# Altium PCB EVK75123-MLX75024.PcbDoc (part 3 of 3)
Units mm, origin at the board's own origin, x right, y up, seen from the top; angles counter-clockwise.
Board outline 80 x 50 mm, 8 copper layers (Top Layer, GND_T, Signal Layer 1, Vcc1, Vcc2, Signal Layer 2, GND_B, Bottom Layer), stack 1.548 mm thick; 222 components, 135 nets, 746 pads, 778 vias.
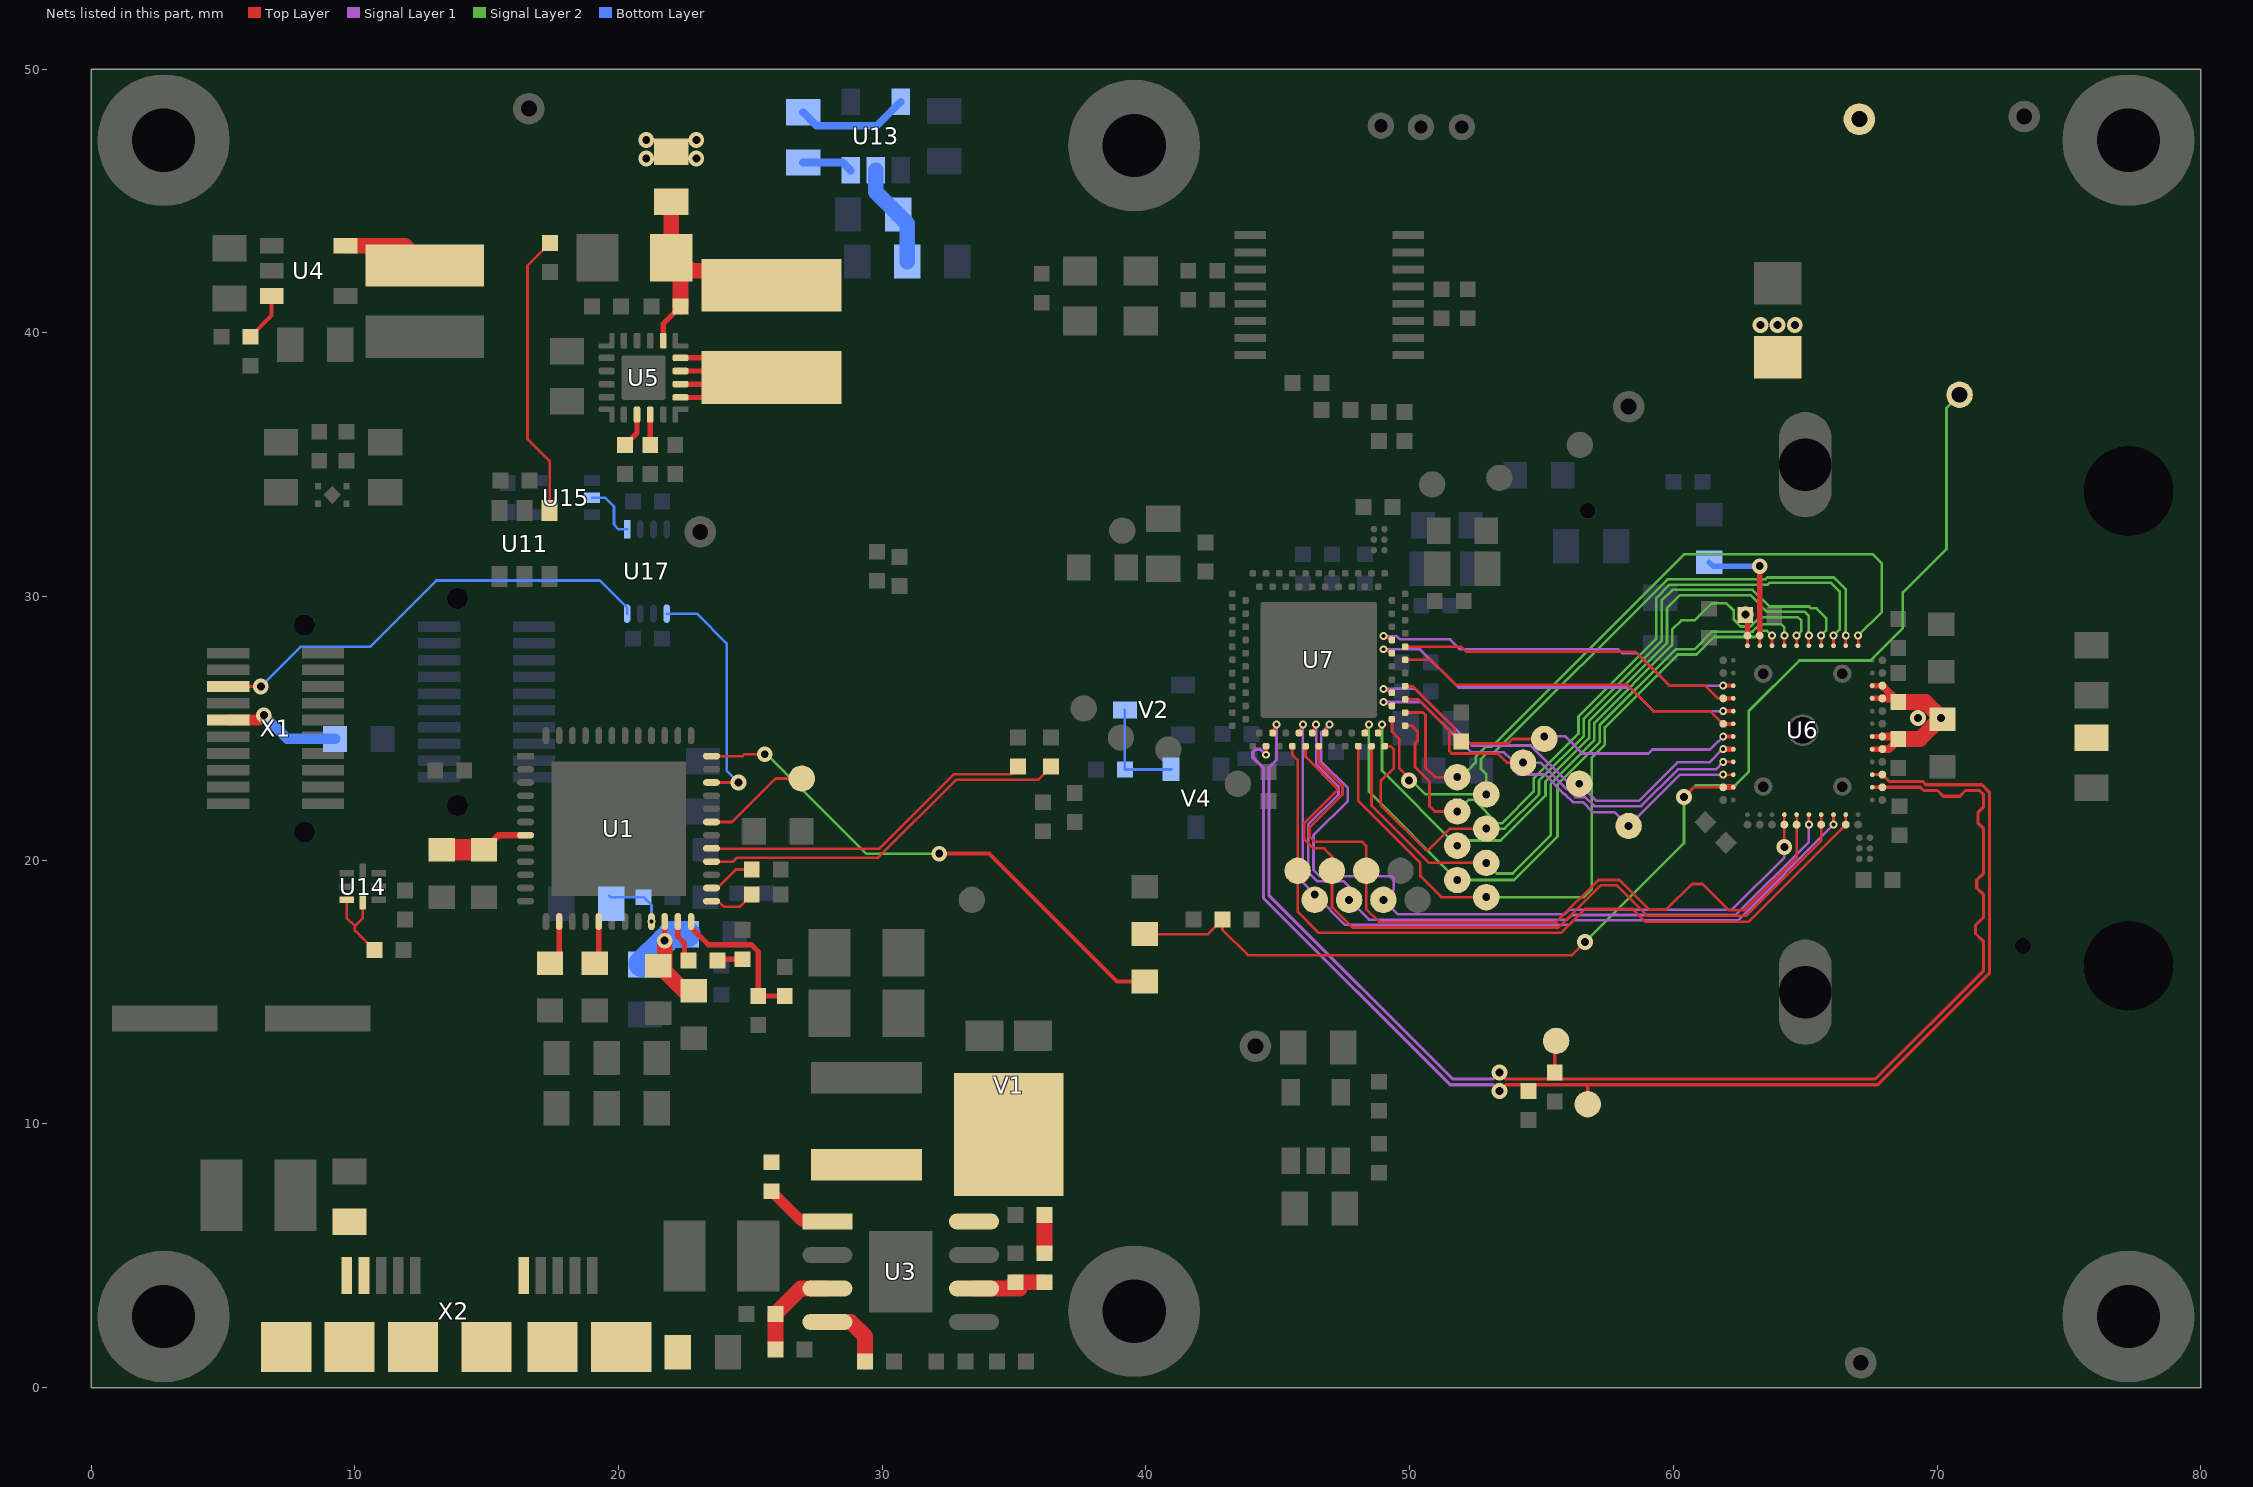
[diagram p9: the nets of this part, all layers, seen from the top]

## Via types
v1: diameter 0.6, hole 0.3, Top Layer to Bottom Layer, tented both sides, 705 vias
v2: diameter 0.3, hole 0.15, Top Layer to Bottom Layer, tented both sides, 49 vias
v3: diameter 0.6, hole 0.3, Top Layer to Bottom Layer, 9 vias
v4: diameter 0.7, hole 0.33, Top Layer to Bottom Layer, 9 vias
v5: diameter 0.5, hole 0.2, Top Layer to Bottom Layer, tented both sides, 6 vias

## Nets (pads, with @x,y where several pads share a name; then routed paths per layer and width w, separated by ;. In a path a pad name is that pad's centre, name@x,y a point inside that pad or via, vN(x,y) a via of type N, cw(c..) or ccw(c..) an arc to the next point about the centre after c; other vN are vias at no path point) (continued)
MLX.COL2: COL2.1 pad.0@64.203,21.35 U6.26 U7.B36 | length 29.1
  Top Layer w0.1: U7.B36@46.8,24.825 v2(46.95,25.15) ; v1(64.203,20.503) pad.0@64.203,21.35 U6.26@64.203,21.733
  Signal Layer 1 w0.1: v2(46.95,25.15) 46.65,24.85 46.65,23.733 47.65,22.733 47.65,22.25 46.35,20.95 46.35,19.633 46.583,19.4 49.3,19.4 49.4,19.3 49.4,18.9 v1(49,18.5) 49.55,17.95 55.875,17.95 56.05,18.125 62.225,18.125 64.203,20.103 v1(64.203,20.503)
MLX.COL3: COL3.1 pad.0@64.669,21.35 U6.27 U7.A39 | length 30
  Top Layer w0.1: U7.A39@46.55,24.325 46.55,23.712 47.45,22.812 47.45,22.5 46.2,21.25 46.2,20.9 46.4,20.7 48.2,20.7 48.35,20.55 COL3.1@48.35,19.6 48.35,18.15 48.85,17.65 55.554,17.65 57.154,19.25 57.95,19.25 59.075,18.125 59.725,18.125 60.7,19.1 61.1,19.1 62.1,18.1 62.683,18.1 64.669,20.086 pad.0@64.669,21.35 U6.27@64.669,21.733
MLX.COL4: COL4.1 pad.0@65.135,21.35 U6.28 U7.B35 | length 29.1
  Top Layer w0.1: U7.B35@46.3,24.825 v2(46.45,25.15) ; v2(65.135,21.35) U6.28@65.135,21.733
  Signal Layer 1 w0.1: v2(46.45,25.15) 46.45,23.65 47.3,22.8 47.3,22.5 46.15,21.35 46.15,19.55 46.5,19.2 47.5,19.2 47.7,19 v1(47.7,18.5) 48.45,17.75 55.958,17.75 56.133,17.925 62.36,17.925 65.135,20.701 v2(65.135,21.35)
MLX.COL5: COL5.1 pad.0@65.601,21.35 U6.29 U7.A38 | length 30
  Top Layer w0.1: U7.A38@46.05,24.325 46.05,23.929 47.25,22.729 47.25,22.65 46,21.4 46,20.8 46.35,20.45 46.75,20.45 47.05,20.15 COL5.1@47.05,19.6 47.05,18.231 47.831,17.45 55.636,17.45 57.236,19.05 57.85,19.05 59,17.9 62.766,17.9 65.601,20.736 pad.0@65.601,21.35 U6.29@65.601,21.733
MLX.COL6: COL6.1 pad.0@66.067,21.35 U6.30 U7.B34 | length 29.1
  Top Layer w0.1: U7.B34@45.8,24.825 v2(45.95,25.15) ; v2(66.067,21.35) U6.30@66.067,21.733
  Signal Layer 1 w0.1: v2(45.95,25.15) 45.95,19.15 v1(46.4,18.7) 47.55,17.55 56.041,17.55 56.216,17.725 62.442,17.725 v2(66.067,21.35)
MLX.COL7: COL7.1 pad.0@66.534,21.35 U6.31 U7.A37 | length 29.9
  Top Layer w0.1: U7.A37@45.55,24.325 45.55,24 45.75,23.8 COL7.1@45.75,19.6 45.75,18.05 46.55,17.25 55.741,17.25 56.641,18.15 58.449,18.15 58.924,17.675 62.859,17.675 pad.0@66.534,21.35 U6.31@66.534,21.733
MLX.CS: CS.1 pad.0@61.886,22.766 R6.2 R8.1 R17.2 R55.1 U6.21 | length 49
  Top Layer w0.1: R8.1@39.95,17.2 42.35,17.2 R6.2@42.9,17.75 42.9,17.363 43.864,16.4 44.236,16.4 56.15,16.4 v1(56.65,16.9) ; v1(60.4,22.4) 60.766,22.766 pad.0@61.886,22.766
  Top Layer w0.2: pad.0@61.886,22.766 U6.21@62.268,22.766
  Signal Layer 2 w0.1: v1(56.65,16.9) 60.4,20.65 v1(60.4,22.4) 60.85,22.85 62.35,22.85 62.85,23.35 62.85,25.65 64.774,27.574 67.474,27.574 68.7,28.8 68.7,30.15 70.35,31.8 70.35,37.15 CS.1@70.85,37.65
MLX.DMIX_N: DM-.1 pad.0@67.919,22.766 R54.1 U6.34 U7.B32 | length 51.9
  Top Layer w0.12: U7.B32@44.8,24.825 v2(44.95,25.15) ; v1(53.4,11.95) 53.64,11.71 67.66,11.71 71.76,15.81 71.76,16.911 71.45,17.221 71.45,17.54 71.76,17.85 71.76,18.69 71.5,18.95 71.5,19.25 71.76,19.51 71.76,21.19 71.55,21.4 71.55,21.814 71.76,22.023 71.76,22.491 71.605,22.645 71.074,22.645 70.854,22.425 70.231,22.425 70.011,22.645 69.48,22.645 69.359,22.766 pad.0@67.919,22.766 U6.34@67.536,22.766 ; R54.1@55.5,11.95 55.5,13.1 DM-.1@55.55,13.15
  Signal Layer 1 w0.12: 44.69,23.54 44.67,23.52 44.67,18.661 51.621,11.71 53.16,11.71 v1(53.4,11.95) ; 44.69,23.541 44.95,23.801 v2(44.95,25.15)
MLX.DMIX_P: DM+.1 pad.0@67.919,23.248 R48.1 U6.35 U7.A35 | length 51.4
  Top Layer w0.12: v2(44.55,24) U7.A35@44.55,24.325 ; v1(53.4,11.25) 53.64,11.49 67.751,11.49 71.98,15.719 71.98,22.582 71.696,22.865 69.571,22.865 69.45,22.986 68.18,22.986 pad.0@67.919,23.248 U6.35@67.536,23.248 ; DM+.1@56.75,10.75 56.75,11.49
  Signal Layer 1 w0.12: v2(44.55,24) 44.339,24.211 44.15,24.211 44.05,24.111 44.05,23.912 44.45,23.512 44.45,18.57 51.53,11.49 53.16,11.49 v1(53.4,11.25)
MLX.L_EN: LEN.1 pad.0@61.886,24.693 R56.1 U6.17 U7.A4 | length 14.1
  Top Layer w0.1: U7.A4@49.825,26.6 50.108,26.6 51.7,25.008 51.7,24.75 R56.1@51.95,24.5 52.025,24.425 53.725,24.425 53.9,24.6 LEN.1@55.1,24.6
  Top Layer w0.15: v2(61.886,24.693) U6.17@62.268,24.693
  Signal Layer 1 w0.1: v1(55.1,24.7) 55.9,24.7 56.55,24.05 59.05,24.05 59.2,24.2 61.386,24.2 61.693,24.507 61.7,24.507 v2(61.886,24.693)
MLX.PFLUSH: FLUSH.1 pad.0@61.886,24.211 U6.18 U7.B3 | length 16.2
  Top Layer w0.1: v2(49,26.5) U7.B3@49.325,26.35
  Top Layer w0.2: v2(61.886,24.211) U6.18@62.268,24.211
  Signal Layer 1 w0.1: v2(49,26.5) 50.208,26.5 52.358,24.35 54.586,24.35 56.034,22.902 v1(56.429,22.902) 57.081,22.25 58.684,22.25 60.145,23.711 61.361,23.711 61.861,24.211 v2(61.886,24.211)
MLX.ROW0: pad.0@63.737,28.517 ROW0.1 U6.8 U7.A42 | length 27.5
  Top Layer w0.1: U7.A42@48.05,24.325 48.05,22.25 50.4,19.9 50.4,19.4 51.2,18.6 v1(52.9,18.6) ; U6.8@63.737,28.135 v2(63.737,28.517)
  Signal Layer 2 w0.1: v1(52.9,18.6) 56.6,18.6 56.901,18.901 56.901,23.888 57.4,24.386 57.4,25.036 60.164,27.8 60.872,27.8 61.537,28.465 63.088,28.465 63.323,28.7 63.554,28.7 v2(63.737,28.517)
MLX.ROW1: pad.0@64.203,28.517 ROW1.1 U6.7 U7.B39 | length 26.3
  Top Layer w0.1: U7.B39@48.3,24.825 v2(48.45,25.15) ; U6.7@64.203,28.135 v2(64.203,28.517)
  Signal Layer 2 w0.1: v2(48.45,25.15) 48.45,22.6 v1(51.8,19.25) 53.95,19.25 55.6,20.9 55.6,22.869 57.2,24.469 57.2,25.119 60.081,28 60.789,28 61.454,28.665 63.005,28.665 63.29,28.95 64.081,28.95 64.203,28.828 v2(64.203,28.517)
MLX.ROW2: pad.0@64.669,28.517 ROW2.1 U6.6 U7.A43 | length 27.5
  Top Layer w0.1: U7.A43@48.55,24.325 48.55,22.078 50.728,19.9 v1(52.9,19.9) ; U6.6@64.669,28.135 v2(64.669,28.517)
  Signal Layer 2 w0.1: v1(52.9,19.9) 53.3,19.5 53.9,19.5 55.35,20.95 55.35,22.902 57,24.552 57,25.202 59.953,28.155 59.953,28.753 60.3,29.1 60.802,29.1 61.452,29.75 62,29.75 62.285,29.465 62.285,29.128 62.549,28.865 62.922,28.865 63.278,29.221 64.711,29.221 64.85,29.082 64.85,28.698 v2(64.669,28.517)
MLX.ROW3: pad.0@65.135,28.517 ROW3.1 U6.5 U7.B40 | length 26.3
  Top Layer w0.1: U7.B40@48.8,24.825 v2(48.95,25.15) ; U6.5@65.135,28.135 v2(65.135,28.517)
  Signal Layer 2 w0.1: v2(48.95,25.15) 48.95,23.4 v1(51.8,20.55) 52,20.75 53.45,20.75 55.15,22.45 55.15,22.985 56.8,24.635 56.8,25.285 59.753,28.238 59.753,29.561 60.242,30.05 62.922,30.05 63.552,29.421 64.979,29.421 65.135,29.265 v2(65.135,28.517)
MLX.ROW4: pad.0@65.601,28.517 ROW4.1 U6.4 U7.A44 | length 27.5
  Top Layer w0.1: U7.A44@49.05,24.325 49.275,24.325 49.4,24.2 49.4,23.5 48.9,23 48.9,22.1 50.6,20.4 50.731,20.4 51.531,21.2 v1(52.9,21.2) ; U6.4@65.601,28.135 v2(65.601,28.517)
  Signal Layer 2 w0.1: v1(52.9,21.2) 53.6,21.2 54.9,22.5 54.9,23.018 56.6,24.718 56.6,25.368 59.553,28.321 59.553,29.842 59.961,30.25 63.005,30.25 63.634,29.621 65.143,29.621 65.214,29.55 65.43,29.55 65.787,29.193 65.787,28.703 v2(65.601,28.517)
MLX.ROW5: pad.0@66.067,28.517 ROW5.1 U6.3 U7.A1 | length 27.5
  Top Layer w0.1: U7.A1@49.825,25.1 50.085,25.1 50.3,24.885 50.3,24.55 50.2,24.45 50.2,23.536 50.75,22.986 50.75,22.05 50.95,21.85 v1(51.8,21.85) ; U6.3@66.067,28.135 v2(66.067,28.517)
  Signal Layer 2 w0.1: v1(51.8,21.85) 52.25,22.3 52.436,22.3 53.336,21.4 53.5,21.4 54.7,22.6 54.7,23.101 56.4,24.801 56.4,25.451 59.353,28.404 59.353,29.953 59.85,30.45 63.564,30.45 63.634,30.521 65.979,30.521 66.3,30.2 66.3,28.75 v2(66.067,28.517)
MLX.ROW6: pad.0@66.534,28.517 ROW6.1 U6.2 U7.B1 | length 26.3
  Top Layer w0.1: U7.B1@49.325,25.35 49.325,24.875 49.6,24.6 49.6,23.5 50.07,23.03 v1(49.975,23.03) ; U6.2@66.534,28.135 v2(66.534,28.517)
  Signal Layer 2 w0.1: v1(49.975,23.03) 50.07,23.03 50.6,22.5 v1(52.9,22.5) 52.9,23.264 52.7,23.464 52.7,23.836 52.964,24.1 53.217,24.1 59.767,30.65 63.481,30.65 63.552,30.721 66.079,30.721 66.534,30.266 v2(66.534,28.517)
MLX.ROW7: pad.0@67,28.517 ROW7.1 U6.1 U7.A2 | length 27.5
  Top Layer w0.1: U7.A2@49.825,25.6 50.5,25.6 50.6,25.5 50.6,23.5 50.95,23.15 v1(51.8,23.15) ; U6.1@67,28.135 v2(67,28.517)
  Signal Layer 2 w0.1: v1(51.8,23.15) 52.088,23.438 52.238,23.438 52.5,23.7 52.5,23.919 52.881,24.3 53.1,24.3 60.4,31.6 67.559,31.6 67.9,31.259 67.9,29.418 v2(67,28.517)
MLX.RST: pad.0@61.886,23.729 RST.1 U6.19 U7.A3 | length 15.3
  Top Layer w0.1: U7.A3@49.825,26.1 50.325,26.1 51.5,24.925 51.5,24.138 51.588,24.05 53.336,24.05 53.686,23.7 v1(54.3,23.7) ; v2(61.886,23.729) 62.205,23.729 62.237,23.698 U6.19@62.268,23.729
  Signal Layer 1 w0.1: v1(54.3,23.7) 54.954,23.7 55.951,22.702 55.975,22.702 56.277,22.4 56.648,22.4 56.998,22.05 58.767,22.05 60.165,23.448 61.604,23.448 v2(61.886,23.729)
MLX.SHUT: pad.0@61.886,23.248 SHUT.1 U6.20 U7.B2 | length 16.6
  Top Layer w0.1: v2(49,26) U7.B2@49.325,25.85 ; v2(61.886,23.248) U6.20@62.268,23.248
  Signal Layer 1 w0.1: v2(49,26) 50.425,26 52.325,24.1 53.564,24.1 53.85,23.814 53.85,23.514 54.114,23.25 55.121,23.25 55.869,22.502 55.891,22.502 56.193,22.2 56.565,22.2 56.945,21.82 57.78,21.82 v1(58.3,21.3) 60.248,23.248 v2(61.886,23.248)
MODE: R1.1 R5.2 U1.24 | length 5.8
  Top Layer w0.2: U1.24@22.75,17.675 22.75,17.45 23.4,16.8 25.033,16.8 25.3,16.533 R1.1@25.3,14.85 R5.2@26.3,14.85
NERR: U1.34 U17.5 | length 9.2
  Top Layer w0.1: U1.34@23.525,22.95 v1(24.55,22.95)
  Bottom Layer w0.1: U17.5@21.825,29.35 22.967,29.35 24.1,28.217 24.1,23.4 v1(24.55,22.95)
nERRH: U17.8 X1.15 | length 17.4
  Top Layer w0.1: X1.15@5.2,26.588 v1(6.438,26.588)
  Bottom Layer w0.1: v1(6.438,26.588) 7.942,28.092 10.583,28.092 13.095,30.605 19.295,30.605 20.325,29.575 U17.8@20.325,29.35
NetC4_1: C4.1 R50.2 | length 1.1
  Top Layer w0.2: C4.1@23.6,16.25 R50.2@24.7,16.25
NetC4_2: C4.2 U1.23 | length 1.5
  Top Layer w0.2: U1.23@22.25,17.675 22.25,17.1 22.5,16.85 C4.2@22.5,16.25
NetC5_2: C5.2 U1.17 | length 1.6
  Top Layer w0.2: C5.2@19.1,16.1 19.25,16.25 U1.17@19.25,17.675
NetC7_2: C7.2 U1.14 | length 1.7
  Top Layer w0.2: C7.2@17.4,16.1 17.75,16.45 U1.14@17.75,17.675
NetC14_1: C14.1 U13.3 | length 1.9
  Bottom Layer w0.3: C14.1@27,46.458 28.5,46.458 U13.3@28.8,46.158
NetC14_2: C14.2 U13.5 | length 4.3
  Bottom Layer w0.3: C14.2@27,48.358 27.508,47.85 29.792,47.85 U13.5@30.7,48.758
NetC16_2: C16.2 C18.2 U1.7 | length 3.4
  Top Layer w0.25: C16.2@14.9,20.4 15.45,20.95 U1.7@16.475,20.95
  Top Layer w0.8: C18.2@13.3,20.4 C16.2@14.9,20.4
NetC38_2: C38.2 pad.0@62.805,28.517 U6.10 | length 1.2
  Top Layer w0.1: U6.10@62.805,28.135 pad.0@62.805,28.517
  Top Layer w0.2: C38.2@62.721,29.3 62.805,29.216 pad.0@62.805,28.517
  Top Layer w0.6: C38.2@62.721,29.3 v1(62.735,29.315)
NetC40_2: C40.2 U5.10 | length 1.3
  Top Layer w0.2: C40.2@20.25,35.75 20.7,36.2 U5.10@20.7,36.9
NetC61_1: C61.1 U3.1 | length 2.6
  Top Layer w0.4: C61.1@25.8,7.45 26.945,6.305 U3.1@27.92,6.305
NetC70_2: C70.2 R29.2 | length 1.1
  Top Layer w0.6: R29.2@36.15,5.15 C70.2@36.15,6.25
NetC71_2: C71.2 R29.1 U3.6 | length 2.9
  Top Layer w0.6: U3.6@33.48,3.765 C71.2@35.215,3.765 ; C71.2@35,4 R29.1@36.15,4
NetC77_2: C77.2 R37.1 R38.1 U13.2 | length 4
  Bottom Layer w0.6: U13.2@29.75,46.158 29.75,45.335 C77.2@30.6,44.485 30.95,44.135 R37.1@30.95,42.7
NetL2_1: L2.1 U4.5 | length 3.3
  Top Layer w0.6: U4.5@9.65,43.3 11.9,43.3 L2.1@12.65,42.55
NetL14_2: L14.2 X2.1 X2.2 X2.6
NetL15_1: L15.1 X2.11 X2.12 X2.13 X2.14 X2.15 X2.16
NetL17_2: L17.2 X1.11 | length 4.5
  Top Layer w0.4: X1.11@5.2,25.318 6.368,25.318 v1(6.55,25.5)
  Bottom Layer w0.4: v1(6.55,25.5) 6.55,25.486 7.436,24.6 L17.2@9.25,24.6
NetR3_1: pad.0@63.271,28.517 R3.1 U6.9 | length 5
  Top Layer w0.1: U6.9@63.271,28.135 pad.0@63.271,28.517
  Top Layer w0.2: pad.0@63.271,28.517 v1(63.271,31.15)
  Bottom Layer w0.2: R3.1@61.35,31.3 61.5,31.15 v1(63.271,31.15)
NetR14_1: R14.1 V2.3 V4.1 | length 4
  Bottom Layer w0.1: V2.3@39.2,25.7 R14.1@39.2,23.439 40.939,23.439 V4.1@40.95,23.45
NetR16_2: R16.2 R20.2 U4.3 | length 1.9
  Top Layer w0.15: R20.2@6.05,39.85 6.85,40.65 U4.3@6.85,41.4
NetR18_2: R18.2 U3.4 | length 2.6
  Top Layer w0.6: U3.4@27.92,2.495 28.805,2.495 29.35,1.95 R18.2@29.35,1
NetR19_2: R19.2 U14.7 U14.8 | length 3.4
  Top Layer w0.1: U14.7@9.7,18.5 9.7,17.8 10,17.5 ; U14.8@10.3,18.4 10.3,17.8 10,17.5 ; R19.2@10.744,16.594 10,17.338 10,17.5
NetR32_1: R32.1 R36.1 U3.3 | length 3.5
  Top Layer w0.6: R36.1@25.95,1.7 R32.1@25.95,2.8 26.915,3.765 U3.3@27.92,3.765
NetR41_2: R41.2 U1.25 | length 1.8
  Top Layer w0.1: U1.25@23.525,18.45 23.781,18.45 24,18.231 24.581,18.231 R41.2@25.05,18.7
NetR42_2: R42.2 U1.26 | length 1.8
  Top Layer w0.1: U1.26@23.525,18.95 23.75,18.95 24.45,19.65 R42.2@25.05,19.65
NetU15_2: U15.2 U17.1 | length 2.2
  Bottom Layer w0.1: U15.2@19,33.75 19.492,33.75 19.827,33.415 19.827,32.731 20.008,32.55 U17.1@20.325,32.55
NINT: nINT.1 U1.31 | length 4.1
  Top Layer w0.1: U1.31@23.525,21.45 24.302,21.45 25.952,23.1 nINT.1@26.95,23.1
NPD: C21.2 R2.1 U1.21 | length 2.3
  Bottom Layer w0.1: C21.2@19.65,18.65 19.7,18.6 R2.1@20.85,18.6 ; R2.1@20.95,18.6 21.25,18.3 v2(21.25,17.675)
OUT0: pad.0@61.886,25.656 U6.15 U7.B6 | length 14.6
  Top Layer w0.1: v2(49,28) U7.B6@49.325,27.85
  Top Layer w0.15: v2(61.886,25.656) U6.15@62.268,25.656
  Signal Layer 1 w0.1: v2(49,28) 50.398,28 51.848,26.55 58.35,26.55 59.244,25.656 v2(61.886,25.656)
OUT1: pad.0@61.886,25.174 U6.16 U7.A6 | length 13.4
  Top Layer w0.1: U7.A6@49.825,27.6 50.798,27.6 51.748,26.65 58.25,26.65 59.244,25.656 61.391,25.656 61.872,25.174 pad.0@61.886,25.174
  Top Layer w0.15: pad.0@61.886,25.174 U6.16@62.268,25.174
OUT2: pad.0@61.886,26.138 U6.14 U7.A7 | length 13.3
  Top Layer w0.1: U7.A7@49.825,28.1 51.95,28.1 52.147,27.903 58.565,27.903 59.848,26.62 61.198,26.62 61.68,26.138 pad.0@61.886,26.138
  Top Layer w0.15: pad.0@61.886,26.138 U6.14@62.268,26.138
OUT3: pad.0@61.886,26.62 U6.13 U7.B7 | length 14.4
  Top Layer w0.1: v2(49,28.5) U7.B7@49.325,28.35
  Top Layer w0.15: v2(61.886,26.62) U6.13@62.268,26.62
  Signal Layer 1 w0.1: v2(49,28.5) 49.5,28.5 49.625,28.375 51.525,28.375 51.9,28 57.904,28 58.054,27.85 58.618,27.85 59.848,26.62 v2(61.886,26.62)
PGMIX: R27.1 U5.11 | length 1.2
  Top Layer w0.2: R27.1@21.2,35.75 U5.11@21.2,36.9
SER.D3: R44.2 U1.28 | length 14.4
  Top Layer w0.1: U1.28@23.525,19.95 24.35,19.95 24.5,20.1 29.847,20.1 32.797,23.05 35.9,23.05 R44.2@36.4,23.55
SER.D4: R45.2 U1.29 | length 12.9
  Top Layer w0.1: U1.29@23.535,20.44 29.89,20.44 32.71,23.26 34.86,23.26 R45.2@35.15,23.55
  Top Layer w0.12: U1.29@23.525,20.45 U1.29@23.535,20.44
SERIO3: R8.2 U1.36 | length 20
  Top Layer w0.1: U1.36@23.525,23.95 24.7,23.95 24.77,24.02 v1(25.545,24.02)
  Top Layer w0.15: v1(32.161,20.25) 34.05,20.25 38.9,15.4 R8.2@39.95,15.4
  Signal Layer 2 w0.1: v1(25.545,24.02) 25.616,24.02 29.386,20.25 v1(32.161,20.25)
SW5V: C61.2 L3.1 U3.8 V1.2
SWMIX: L4.1 U5.13 U5.14 U5.15 U5.16 | length 13.9
  Top Layer w0.2: U5.13@22.35,37.55 25.05,37.55 L4.1@25.55,38.05 ; U5.14@22.35,38.05 L4.1@25.55,38.05 ; U5.15@22.35,38.55 L4.1@25.55,38.55 ; U5.16@22.35,39.05 25.05,39.05 L4.1@25.55,38.55 ; L4.1@25.55,38.05 L4.1@25.8,38.3 L4.1@25.55,38.55
V_MIX: R9.2 U11.1 | length 10.8
  Top Layer w0.1: U11.1@17.387,33.258 17.387,35.143 16.55,35.98 16.55,42.55 R9.2@17.4,43.4
VDD33: C3.1 C84.2 C85.2 L9.2 U1.22 | length 5.4
  Top Layer w0.2: v1@21.75,17 U1.22@21.75,17.675
  Top Layer w0.6: v1(21.75,16.95) 21.75,15.79 22.49,15.05 C3.1@22.85,15.05
  Bottom Layer w1: C85.2@20.875,16.075 v1(21.75,16.95) 22,17.2 L9.2@22.6,17.2
VMIX: C23.2 C34.2 C36.2 C37.2 C89.1 pad.0@67.919,24.211 pad.0@67.919,24.693 pad.0@67.919,26.62 pad.0@67.919,26.138 R49.1 U6.37 U6.38 U6.41 U6.42 VMIXH.1 | length 8.1
  Top Layer w0.2: U6.37@67.536,24.211 pad.0@67.919,24.211 ; U6.38@67.536,24.693 pad.0@67.919,24.693 ; U6.41@67.536,26.138 pad.0@67.919,26.138 ; U6.42@67.536,26.62 pad.0@67.919,26.62
  Top Layer w0.3: pad.0@67.919,24.211 68.17,24.211 C34.2@68.559,24.6 ; pad.0@67.919,24.693 C34.2@68.499,24.693 ; pad.0@67.919,26.138 C36.2@68.4,26.138 ; pad.0@67.919,26.62 C36.2@68.538,26
  Top Layer w0.6: C36.2@68.538,26 69.55,26 v1(70.15,25.4) 69.35,24.6 C34.2@68.559,24.6
  other v1: 69.275,25.4 63.3,40.3 63.95,40.3 64.6,40.3 21.05,46.613 22.95,46.613 21.05,47.313 22.95,47.313
VOMIX: C35.2 L4.2 R25.2 R49.2 U5.1 | length 8.7
  Top Layer w0.2: U5.1@21.7,39.7 21.7,40.35 R25.2@22.35,41
  Top Layer w0.6: R49.2@22,44.963 C35.2@22,42.85 ; R25.2@22.35,41 22.35,42.5 C35.2@22,42.85 ; L4.2@24.85,42.35 22.75,42.35 22.25,42.85 C35.2@22,42.85
pads on no net: LH1.4 LH1.8 LH2.PS1 LH2.PS2 U1.3 U1.4 U1.5 U1.11 U1.12 U1.13 U1.16 U1.27 U1.43 U1.44 U2.1 U5.A1 U5.A2 U5.A3 U5.A4 U7.A23 U8.C1 U9.C1 U10.8 U10.9 U10.12 U10.14 U10.15 U10.16 U12.4 U15.1 X1.A1 X1.A2 X2.4 X4.9 X4.10 X4.11 X4.12 X4.13 X4.14 X4.15 X4.16 X4.17 X4.19 X4.A1 X4.A2
copper on no net:
  other v1: 41.6,29.7 51.6,39.85 52.3,39.85

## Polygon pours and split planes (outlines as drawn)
no net on BotDimHUM "spare_HUM" (hatched 45Degree grid 0.4 track 0.05, remove dead copper, pour order 0): 80,45 74.7,45 74.7,30.5 58.5,30.5 58.5,18.5 74.7,18.5 74.7,5 80,5
GND on Bottom Layer "GND" (solid, remove dead copper, pour order 21): 0.2,49.8 79.8,49.8 79.8,37.8 79.8,0.2 71,0.2 0.2,0.2 0.2,11.2
24V on Bottom Layer "24V" (solid, remove dead copper, pour order 16): 26.65,2.25 10.05,2.25 5.8,6.5 5.8,20.8 7.7,22.7 10.25,25.25 14,25.25 14,22.175 10.95,19.125 10.95,11.1 14.45,7.6 21.35,7.6 25.45,7.6 26.2,6.85 26.65,6.4 26.65,3.9
GND on Top Layer "GND" (solid, remove dead copper, pour order 17): 0.2,49.8 79.8,49.8 79.8,37.8 79.8,0.2 71,0.2 0.2,0.2 0.2,11.2
GND on Signal Layer 2 "GND" (solid, remove dead copper, pour order 19): 0.2,49.8 79.8,49.8 79.8,37.8 79.8,0.2 71,0.2 0.2,0.2 0.2,11.2
GND on Signal Layer 1 "GND" (solid, remove dead copper, pour order 18): 0.2,49.8 79.8,49.8 79.8,37.8 79.8,0.2 71,0.2 0.2,0.2 0.2,11.2
GND on GND_T (split plane): 79.49,0.51 0.51,0.51 0.51,49.49 79.49,49.49
1V8 on Vcc1 (split plane): 2.193,39.093 2.224,39.069 2.261,39.054 2.3,39.049 7.481,39.049 10.436,36.093 10.468,36.069 10.504,36.054 10.543,36.049 22.187,36.049 23.193,35.043 23.224,35.019 23.261,35.004 23.3,34.999 40.35,34.999 40.389,35.004 40.426,35.019 40.457,35.043 44.613,39.199 53.187,39.199 54.799,37.587 54.799,34.5 54.804,34.461 54.819,34.424 54.843,34.393 55.061,34.175 53.887,33.001 52.163,33.001 51.551,33.613 51.551,34.75 51.546,34.789 51.531,34.826 51.507,34.857 51.258,35.106 51.227,35.13 51.19,35.145 51.151,35.15 50.549,35.15 50.51,35.145 50.473,35.13 50.442,35.106 48.843,33.507 46.543,31.207 46.519,31.176 46.513,31.161 46.504,31.139 46.499,31.1 46.499,29.665 46.504,29.625 46.513,29.604 46.519,29.589 46.543,29.558 47.658,28.443 47.689,28.419 47.725,28.404 47.765,28.399 49.999,28.399 49.999,26.518 50.004,26.479 50.019,26.443 50.043,26.411 55.611,20.843 55.643,20.819 55.679,20.804 55.718,20.799 69.124,20.799 69.124,0.301 0.301,0.301 0.301,40.985
VMIX on Vcc1 (split plane): 79.699,0.301 69.426,0.301 69.426,23.925 69.421,23.964 69.412,23.986 69.406,24.001 69.382,24.032 63.601,29.813 63.601,30.45 63.596,30.489 63.581,30.526 63.557,30.557 59.832,34.282 59.801,34.306 59.786,34.312 59.764,34.321 59.725,34.326 55.338,34.326 55.101,34.563 55.101,37.65 55.096,37.689 55.085,37.715 55.081,37.726 55.057,37.757 53.357,39.457 53.326,39.481 53.311,39.487 53.289,39.496 53.25,39.501 44.55,39.501 44.511,39.496 44.489,39.487 44.474,39.481 44.443,39.457 40.287,35.301 23.363,35.301 22.357,36.307 22.326,36.331 22.289,36.346 22.25,36.351 10.606,36.351 7.65,39.307 7.619,39.331 7.582,39.346 7.543,39.351 2.363,39.351 0.301,41.413 0.301,49.699 79.699,49.699
GND on Vcc1 (split plane): 63.299,30.387 63.299,29.75 63.304,29.711 63.313,29.689 63.319,29.674 63.343,29.643 69.124,23.862 69.124,21.101 55.781,21.101 50.301,26.581 50.301,28.499 51.5,28.499 51.539,28.504 51.561,28.513 51.576,28.519 51.607,28.543 54.013,30.949 55.55,30.949 55.589,30.954 55.611,30.963 55.626,30.969 55.657,30.993 56.857,32.193 56.881,32.224 56.896,32.261 56.901,32.3 56.901,34.024 59.662,34.024
1V8A on Vcc1 (split plane): 51.249,34.687 51.249,33.55 51.254,33.511 51.269,33.474 51.293,33.443 51.993,32.743 52.024,32.719 52.061,32.704 52.1,32.699 53.95,32.699 53.989,32.704 54.011,32.713 54.026,32.719 54.057,32.743 55.338,34.024 56.599,34.024 56.599,32.363 55.487,31.251 53.95,31.251 53.911,31.246 53.885,31.235 53.874,31.231 53.843,31.207 51.437,28.801 50.15,28.801 50.111,28.796 50.074,28.781 50.043,28.757 49.987,28.701 47.827,28.701 46.801,29.727 46.801,31.037 49.057,33.293 50.611,34.847 51.089,34.847
5V0 on Vcc2 (split plane): 6.599,43.537 6.599,41.813 3.643,38.857 3.619,38.826 3.604,38.789 3.599,38.75 3.599,34.75 3.604,34.711 3.619,34.674 3.643,34.643 4.593,33.693 4.624,33.669 4.639,33.663 4.661,33.654 4.7,33.649 7.175,33.649 7.214,33.654 7.251,33.669 7.282,33.693 13.838,40.249 23,40.249 23.039,40.254 23.076,40.269 23.107,40.293 26.513,43.699 30.037,43.699 30.53,43.206 30.53,41.669 23.066,34.205 22.409,34.205 22.051,34.563 22.051,35.3 22.046,35.339 22.031,35.376 22.007,35.407 21.557,35.857 21.526,35.881 21.489,35.896 21.45,35.901 14.45,35.901 14.411,35.896 14.374,35.881 14.343,35.857 12.893,34.407 12.869,34.376 12.854,34.339 12.849,34.3 12.849,32.35 12.849,30.613 8.093,25.857 8.069,25.826 8.054,25.789 8.049,25.75 8.049,13.6 8.054,13.561 8.069,13.524 8.093,13.493 14.093,7.493 14.124,7.469 14.161,7.454 14.2,7.449 24.75,7.449 24.789,7.454 24.811,7.463 24.826,7.469 24.857,7.493 27.257,9.893 27.281,9.924 27.296,9.961 27.301,10 27.301,17.387 27.863,17.949 29.287,17.949 39.143,8.093 39.174,8.069 39.211,8.054 39.25,8.049 45.337,8.049 46.174,7.212 46.174,0.301 0.301,0.301 0.301,44.299 5.837,44.299
1V8D on Vcc2 (split plane): 49.749,30.945 48.311,29.507 46.668,27.864 46.644,27.833 46.638,27.818 46.629,27.796 46.624,27.757 46.624,27.438 43.55,24.364 41.351,26.563 41.351,31.237 41.613,31.499 42.507,31.499 44.555,29.451 44.586,29.427 44.601,29.42 44.623,29.411 44.662,29.406 46.358,29.406 46.397,29.411 46.418,29.42 46.433,29.427 46.465,29.451 48.975,31.961 49.749,31.961
3V3 on Vcc2 (split plane): 79.699,0.301 46.477,0.301 46.477,7.274 46.472,7.314 46.457,7.35 46.433,7.381 45.507,8.307 45.476,8.331 45.439,8.346 45.4,8.351 39.313,8.351 29.457,18.207 29.426,18.231 29.411,18.237 29.389,18.246 29.35,18.251 27.8,18.251 27.761,18.246 27.724,18.231 27.693,18.207 27.043,17.557 27.019,17.526 27.004,17.489 26.999,17.45 26.999,10.063 24.687,7.751 14.263,7.751 8.351,13.663 8.351,25.687 13.107,30.443 13.131,30.474 13.146,30.511 13.151,30.55 13.151,32.35 13.151,34.237 14.513,35.599 21.387,35.599 21.749,35.237 21.749,34.5 21.754,34.461 21.763,34.439 21.769,34.424 21.793,34.393 22.239,33.947 22.27,33.923 22.307,33.908 22.346,33.903 23.128,33.903 23.167,33.908 23.189,33.917 23.204,33.923 23.235,33.947 30.788,41.5 30.812,41.531 30.827,41.568 30.832,41.607 30.832,43.269 30.827,43.308 30.812,43.345 30.788,43.376 30.207,43.957 30.176,43.981 30.161,43.987 30.139,43.996 30.1,44.001 26.45,44.001 26.411,43.996 26.374,43.981 26.343,43.957 22.937,40.551 13.775,40.551 13.736,40.546 13.699,40.531 13.668,40.507 7.112,33.951 4.763,33.951 3.901,34.813 3.901,38.687 6.857,41.643 6.881,41.674 6.896,41.711 6.901,41.75 6.901,43.6 6.896,43.639 6.881,43.676 6.857,43.707 6.007,44.557 5.976,44.581 5.961,44.587 5.939,44.596 5.9,44.601 0.301,44.601 0.301,49.699 79.699,49.699
3V3A on Vcc2 (split plane): 61.649,28.937 61.649,27.413 46.187,11.951 43.563,11.951 43.301,12.213 43.301,13.936 45.307,15.942 45.331,15.973 45.346,16.01 45.351,16.049 45.351,18.387 48.507,21.543 48.531,21.574 48.546,21.611 48.551,21.65 48.551,25.75 48.547,25.783 51.457,28.693 51.481,28.724 51.496,28.761 51.501,28.8 51.501,30.337 51.813,30.649 57.2,30.649 57.239,30.654 57.276,30.669 57.307,30.693 58.6,31.986
3V3CC on Vcc2 (split plane): 48.249,25.687 48.249,21.713 45.137,18.601 43.463,18.601 42.151,19.913 42.151,21.437 43.657,22.943 43.681,22.975 43.696,23.011 43.702,23.05 43.702,24.087 46.775,27.161
1V8ADC on Vcc2 (split plane): 58.449,32.887 58.449,32.263 57.137,30.951 51.75,30.951 51.711,30.946 51.685,30.935 51.674,30.931 51.643,30.907 51.243,30.507 51.219,30.476 51.213,30.461 51.204,30.439 51.199,30.4 51.199,28.863 48.35,26.014 46.926,27.438 46.926,27.695 48.525,29.293 50.007,30.775 50.031,30.807 50.046,30.843 50.051,30.882 50.051,34.086 50.714,34.749 56.587,34.749
GND on GND_B (split plane): 79.49,0.51 0.51,0.51 0.51,49.49 79.49,49.49

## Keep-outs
Keep-Out Layer:
  the board outline again, w0.2

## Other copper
Top Layer:
  rectangle net GND: 63.05,22.425 66.746,27.425
  region net GND: 36.45,13.95 33.15,13.95 33.15,12.75 36.45,12.75
  region net 24V: 10.45,8.7 6.95,8.7 6.95,7.7 10.45,7.7
  region net MH2: 42.55,47.1 cw(c39.55,47.1) 39.55,44.1 cw(c39.55,47.1) 36.55,47.1 36.55,49.8 42.55,49.8
  region net MH6: 36.55,2.9 cw(c39.55,2.9) 39.55,5.9 cw(c39.55,2.9) 42.55,2.9 42.55,0.2 36.55,0.2
  region net MH3: 74.25,2.7 cw(c77.25,2.7) 77.25,5.7 79.796,5.7 79.796,0.204 74.25,0.204
  region net MH5: 74.25,47.3 ccw(c77.25,47.3) 77.25,44.3 79.796,44.3 79.796,49.796 74.25,49.796
  region net MH1: 5.75,2.7 ccw(c2.75,2.7) 2.75,5.7 0.204,5.7 0.204,0.204 5.75,0.204
  region net MH4: 5.75,47.3 cw(c2.75,47.3) 2.75,44.3 0.204,44.3 0.204,49.796 5.75,49.796
  pour cut-out: 22.762,39.617 22.267,40.112 19.633,40.112 19.138,39.617 19.138,36.987 19.637,36.488 22.267,36.488 22.762,36.983
  region net 5V0: 17.4,37.4 17.4,36.45 17.7,36.15 18.4,36.15 18.7,36.45 18.7,37.4
  region net GND: 17.4,39.3 17.4,38.35 17.7,38.05 18.4,38.05 18.7,38.35 18.7,39.3
  region net GND: 19.35,42.2 20.3,42.2 20.6,42.5 20.6,43.2 20.3,43.5 19.35,43.5
  pour cut-out: 49.28,32.638 49.141,32.777 48.453,32.777 48.386,32.71 48.386,31.688 48.568,31.506 49.099,31.506 49.28,31.687
  region net VMIX: 22,47.613 21.05,47.613 20.75,47.313 20.75,46.613 21.05,46.313 22,46.313
  region net VMIX: 22,46.313 22.95,46.313 23.25,46.613 23.25,47.313 22.95,47.613 22,47.613
  region net 3V3: 69.9,27.6 74.35,27.6 75.4,26.55 75.4,25.75 74.5,25.75 73.55,26.7 69.9,26.7
  region net VMIX: 69.8,25.9 73.4,25.9 74.15,25.15 75.2,25.15 75.5,24.85 75.5,24.15 73.3,24.15 72.55,24.9 69.8,24.9
  pour cut-out: 16,25.2 24,25.2 24,17.2 16,17.2
  pour cut-out: 43.047,31.099 50.05,31.099 50.05,24.1 43.047,24.1
  region net NetL14_2: 10.55,6.85 9,6.85 9,3.55 10.55,3.55
  region net GND: 4.4,24.9 6.55,24.9 6.85,24.6 6.85,22.25 6.55,21.95 4.4,21.95
  region net 24V: 8,24.9 10.15,24.9 10.45,24.6 10.45,22.25 10.15,21.95 8,21.95
  region net 5V0: 27.2,15 27.2,11.25 27.3,11.15 30.6,11.15 30.6,12 29.55,13.05 29.55,15
  region net SW5V: 25.5,8.85 25.7,9.05 33.45,9.05 34.4,8.1 34.4,6.45 33.95,6 32.4,6 32.1,6.3 30.3,6.3 28.75,7.85 26.5,7.85
  region net VMIX: 63.05,39.75 63.05,40.35 63.2,40.5 64.7,40.5 64.85,40.35 64.85,39.75
  region net GND: 63.05,42.55 63.05,43.15 63.2,43.3 64.7,43.3 64.85,43.15 64.85,42.55
  pour cut-out: 61.95,28.35 67.75,28.35 67.75,21.5 61.95,21.5
  region net NetL14_2: 16.6,3.55 15.4,3.55 12.7,6.25 9,6.25 9,7.25 14.75,7.25 16.6,5.4
  region net 24V: 6.6,14.2 6.6,14.9 6.8,15.1 6.9,15.1 7,15.2 10.2,15.2 10.25,15.15 10.35,15.15 10.6,14.9 10.6,14.2
  region net GND: 3.45,8.15 3.45,9.1 3.15,9.4 2.45,9.4 2.15,9.1 2.15,8.15
  region net GND: 23.35,5.8 23.35,6.75 23.05,7.05 22.35,7.05 22.05,6.75 22.05,5.8
  region net GND: 22.05,4.2 22.05,3.25 22.35,2.95 23.05,2.95 23.35,3.25 23.35,4.2
  region net 24V: 24.65,6.35 24.05,6.35 23.75,6.05 23.75,3.95 24.05,3.65 24.65,3.65
  region net 24V: 7.1,8.65 6.5,8.65 6.2,8.35 6.2,6.25 6.5,5.95 7.1,5.95
  region net GND: 4.45,6.5 4.45,5.55 4.75,5.25 5.45,5.25 5.75,5.55 5.75,6.5
  region net GND: 5.75,8.1 5.75,9.05 5.45,9.35 4.75,9.35 4.45,9.05 4.45,8.1
  region net GND: 34.53,13.4 34.53,14.35 34.23,14.65 33.53,14.65 33.23,14.35 33.23,13.4
  region net GND: 36.35,13.4 36.35,14.35 36.05,14.65 35.35,14.65 35.05,14.35 35.05,13.4
  region net 5V0: 27.2,14.7 29.25,14.7 29.55,15 29.55,17.1 29.25,17.4 27.2,17.4
  region net GND: 31.45,14.75 32.05,14.75 32.35,15.05 32.35,17.15 32.05,17.45 31.45,17.45
  region net NetL15_1: 22.75,2 22.25,2.5 6.45,2.5 6.45,0.6 22.65,0.6 22.75,0.7
  pour cut-out: 67.05,21.079 67.45,21.079 67.679,20.85 67.679,20.079 67.432,19.832 67.068,19.832 66.821,20.079 66.821,20.85
  region net VMIX: 68.238,26.3 68.238,24.312 68.25,24.3 69.05,24.3 70.1,25.35 69.15,26.3
Bottom Layer:
  rectangle net GND: 63.05,22.425 66.746,27.425
  region net MH2: 36.55,47.1 ccw(c39.55,47.1) 39.55,44.1 ccw(c39.55,47.1) 42.55,47.1 42.55,49.8 36.55,49.8
  region net MH6: 42.55,2.9 ccw(c39.55,2.9) 39.55,5.9 ccw(c39.55,2.9) 36.55,2.9 36.55,0.2 42.55,0.2
  region net MH3: 77.25,5.7 ccw(c77.25,2.7) 74.25,2.7 74.25,0.2 79.796,0.2 79.796,5.7
  region net MH5: 77.25,44.3 cw(c77.25,47.3) 74.25,47.3 74.25,49.8 79.796,49.8 79.796,44.3
  region net MH1: 2.75,5.7 cw(c2.75,2.7) 5.75,2.7 5.75,0.2 0.204,0.2 0.204,5.7
  region net MH4: 2.75,44.3 ccw(c2.75,47.3) 5.75,47.3 5.75,49.8 0.204,49.8 0.204,44.3
  region net GND: 17.6,25.25 15.35,25.25 15.15,25.05 15.15,23.25 15.45,22.95 17.6,22.95
  region net 1V8A: 56.25,34.95 56.25,33.75 56.05,33.55 56.05,32.9 56.4,32.55 56.4,31.266 55.25,31.266 55.25,35 55.35,35.1 56.1,35.1
Vcc1 (plane layer: these items are gaps in the copper):
  lines w0.3: 0,41.5 2.3,39.2 7.543,39.2 10.543,36.2 22.25,36.2 23.3,35.15 40.35,35.15 44.55,39.35 53.25,39.35 54.95,37.65 54.95,34.5 55.275,34.175 ; 56.75,34.175 56.75,32.3 55.55,31.1 53.95,31.1 51.5,28.65 50.15,28.65 ; 69.275,0 69.275,23.925 63.45,29.75 63.45,30.45 59.725,34.175 55.275,34.175 ; 69.275,20.95 55.718,20.95 50.15,26.518 50.15,28.65 ; 50.15,28.65 50.05,28.55 47.765,28.55 46.65,29.665 46.65,31.1 48.95,33.4 50.549,34.999 51.151,34.999 51.4,34.75 51.4,33.55 52.1,32.85 53.95,32.85 55.275,34.175
Vcc2 (plane layer: these items are gaps in the copper):
  lines w0.3: 0,44.45 5.9,44.45 6.75,43.6 6.75,41.75 3.75,38.75 3.75,34.75 4.7,33.8 7.175,33.8 13.775,40.4 23,40.4 26.45,43.85 30.1,43.85 30.681,43.269 30.681,41.607 23.128,34.054 22.346,34.054 21.9,34.5 21.9,35.3 21.45,35.75 14.45,35.75 13,34.3 13,32.35 13,30.55 8.2,25.75 8.2,13.6 14.2,7.6 24.75,7.6 27.15,10 27.15,17.45 27.8,18.1 29.35,18.1 39.25,8.2 45.4,8.2 46.326,7.274 46.326,0 ; 48.35,25.8 51.35,28.8 51.35,30.4 51.75,30.8 57.2,30.8 58.6,32.2 ; 49.9,33.3 49.9,32.112 48.912,32.112 46.358,29.558 44.662,29.558 42.569,31.65 41.55,31.65 41.2,31.3 41.2,26.5 43.55,24.15 ; 43.55,24.15 46.775,27.375 ; 43.55,24.15 43.55,23.05 42,21.5 42,19.85 43.4,18.45 45.2,18.45 ; 45.2,18.45 45.2,16.049 43.15,13.999 43.15,12.15 43.5,11.8 46.25,11.8 61.8,27.35 61.8,29 58.6,32.2 ; 45.2,18.45 48.4,21.65 48.4,25.75 46.775,27.375 ; 46.775,27.375 46.775,27.757 48.418,29.4 49.9,30.882 49.9,34.149 50.651,34.9 56.65,34.9 58.6,32.95 58.6,32.2

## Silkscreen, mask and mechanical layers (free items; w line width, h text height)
Top Overlay:
  drawing of 1007 lines, arcs and shapes, not listed
  text "www.bluetechnix.com" at 61.1,5.357 h0.8
Bottom Overlay:
  circle w0.254: c65,14 r2.2
  circle w0.254: c65,16 r2.2
  circle w0.254: c65,34 r2.2
  circle w0.254: c65,36 r2.2
Top Solder:
  drawing of 1010 lines, arcs and shapes, not listed
  text "E" at 40.627,6.5 h5.5
  text "www.bluetechnix.com" at 61.111,5.35 h0.8
  text ".prj_Vers" at 53.6,1 h0.9
Bottom Solder:
  rectangle: 63.05,0 80.1,50
  rectangle: 44.355,25.405 48.745,29.795
Boardoutline:
  the board outline again, w0.3
Top Text:
  circle w0.5: c64.902,24.934 r8.5
Cutout:
  lines w2.4: -1.1,4.3 -1.1,46.5 4.2,46.5 ; -1,4.3 4.2,4.3 ; 8.65,4.3 41.2,4.3 ; 8.65,46.5 41.2,46.5 ; 45.65,4.3 71.35,4.3 ; 45.65,46.5 71.35,46.5 ; 75.8,4.3 81.1,4.3 ; 75.8,46.5 81,46.5 ; 81.1,4.325 81.1,46.5
Score:
  lines w0.4: 0,0.4 0,50.4 ; 80,0.4 80,50.4
TopDimHUM:
  circle w0.1: c2.75,47.3 r1.2
  lines w0: 40.5,7.65 40.5,8.125 ; 42.5,7.65 42.5,8.1
  lines w0.1: 64.6,25 65.4,25 ; 65,24.55 65,25.35
BotDimHUM:
  lines w0.01: 64,14 ccw(c65,14) 66,14 66,16 ccw(c65,16) 64,16 64,14 ; 64,34 ccw(c65,34) 66,34 66,36 ccw(c65,36) 64,36 64,34
  text "solder mask" at 74.55,21.9 h1
  text "spared for cooling" at 77.5,19.9 h1

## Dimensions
75,25 to 80,50 on BotDimHUM
74.7,30.5 to 80,50 on BotDimHUM
74.7,18.5 to 74.7,30.5 on BotDimHUM
80,0 to 74.7,18.5 on BotDimHUM
74.7,5 to 58.5,18.5 on BotDimHUM
80,0 to 74.7,5 on BotDimHUM
0,50 to 0,0 on TopDimHUM
0,0 to 80,0 on TopDimHUM
40.5,7.65 to 42.5,7.65 on TopDimHUM
65,17 to 65,13 on BotDimHUM
65,35 to 80,50 on BotDimHUM
64,14 to 66,14 on BotDimHUM
0,0 to 14.2,26 on BotDimHUM
0,0 to 15,25.2 on BotDimHUM
2.75,47.3 to 4.9,49.3 on TopDimHUM
65,25.35 to 80,50 on TopDimHUM
0,50 to 39.55,47.1 on TopDimHUM
2.75,47.3 to 0,50 on TopDimHUM
2.75,2.7 to 2.75,47.3 on TopDimHUM
0,0 to 2.75,2.7 on TopDimHUM
39.55,47.1 to 80,50 on TopDimHUM
80,0 to 77.25,2.7 on TopDimHUM
77.25,2.7 to 80,0 on TopDimHUM
0,0 to 7.1,-1.2 on TopDimHUM
0,0 to 2.75,2.7 on TopDimHUM
80,0 to 0,0 on BotDimProd
71.5,47 to 80,0 on BotDimProd
80,0 to 3.5,29 on BotDimProd
80,0 to 43.5,8 on BotDimProd
0,50 to 0,0 on BotDimProd
71,47.5 to 0,50 on BotDimProd
3,29.5 to 0,50 on BotDimProd
43,8.5 to 0,50 on BotDimProd
0,50 to 0,0 on TopDimProd
2.4,28.65 to 80,0 on TopDimProd
80,0 to 45.5,47 on TopDimProd
80,0 to 62.5,2 on TopDimProd
0,50 to 45,47.5 on TopDimProd
0,0 to 80,0 on TopDimProd
0,50 to 62,2.5 on TopDimProd
0,50 to 1.9,29.15 on TopDimProd
80,50 to 64.6,25 on TopDimHUM
65,13 to 0,0 on BotDimHUM
65,33 to 65,17 on BotDimHUM
77.25,47.3 to 80,50 on TopDimHUM
6.4,-1.05 to 20.6,-1.2 on TopDimHUM
6.3,25 to 0,0 on TopDimHUM
7,25.806 to 0,50 on TopDimHUM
